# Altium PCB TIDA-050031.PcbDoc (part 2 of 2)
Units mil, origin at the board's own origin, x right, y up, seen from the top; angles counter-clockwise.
Board outline 3300 x 2400 mil, 4 copper layers (Top Layer, Signal Layer 1, Signal Layer 2, Bottom Layer), stack 65.634 mil thick; 87 components, 39 nets, 206 pads, 178 vias.
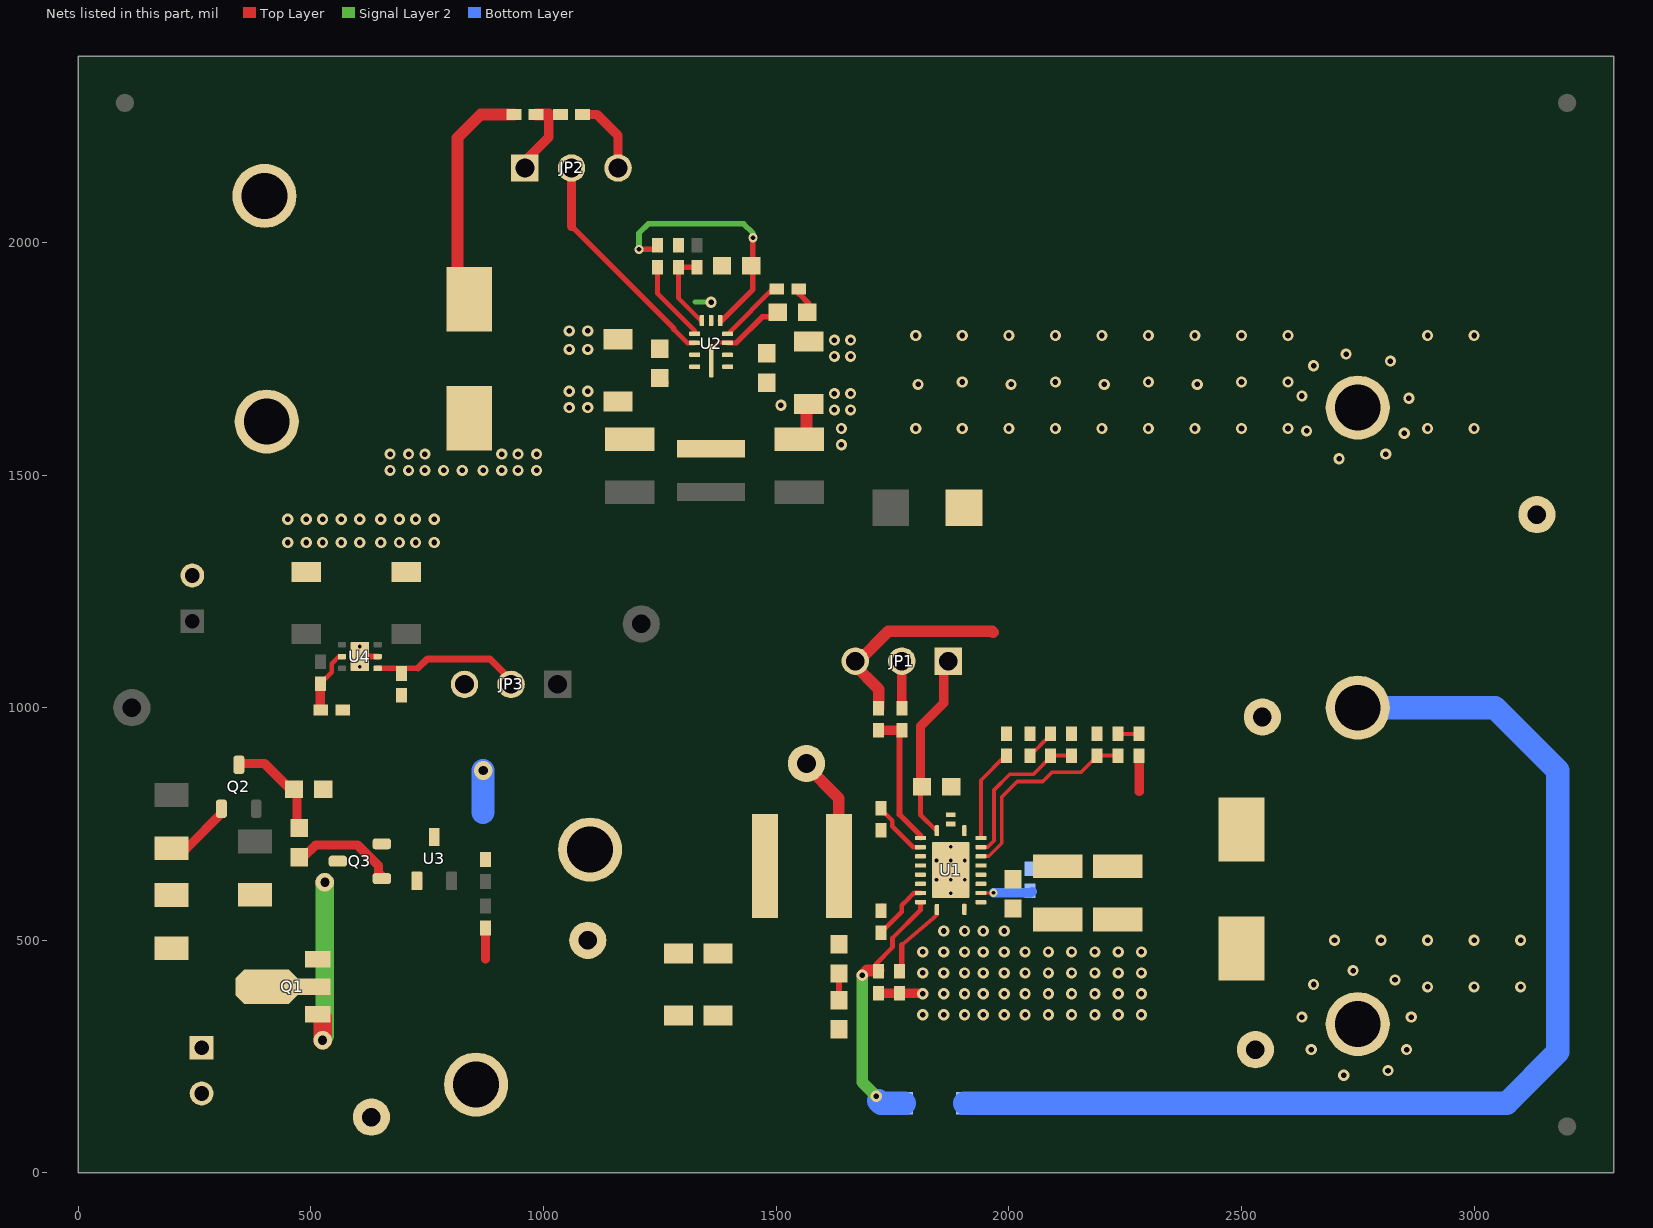
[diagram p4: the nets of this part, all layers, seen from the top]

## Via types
v1: diameter 24, hole 12, Top Layer to Bottom Layer, 156 vias
v2: diameter 19.68, hole 7.87, Top Layer to Bottom Layer, 10 vias
v3: diameter 20, hole 10, Top Layer to Bottom Layer, 4 vias
v4: diameter 24, hole 12, Top Layer to Bottom Layer, tented bottom, 4 vias
v5: diameter 40, hole 20, Top Layer to Bottom Layer, 3 vias
v6: diameter 18, hole 8, Top Layer to Bottom Layer, 1 vias

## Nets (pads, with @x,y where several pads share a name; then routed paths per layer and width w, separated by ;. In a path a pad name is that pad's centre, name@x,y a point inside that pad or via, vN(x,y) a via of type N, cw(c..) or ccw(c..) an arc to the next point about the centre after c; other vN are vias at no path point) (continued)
AGND: C8.2 C10.2 C12.2 C14.1 JP1.3 NT2.2 NT3.2 R2.1 R6.1 U1.20 | length 467.2
  Top Layer w8: C14.1@1876,814.79 C14.1@1876,831 ; U1.20@1904.53,736.47 U1.20@1904.53,735.65 U1.20@1905,735.65 ; C8.2@2043,941 C8.2@2047,945 ; R2.1@2189,945 2189,944 R2.1@2189.38,943.62
  Top Layer w25: JP1.3@1665,1095 1720,1040 C12.2@1720,998.62 ; JP1.3@1670,1100 1677,1100 1741,1164 1964,1164 1966,1162
AGND1: C29.1 JP2.3 NT1.1 R11.1 R13.1 U2.6 | length 203
  Top Layer w20: R11.1@1083.62,2275 1115,2275 1160,2230 JP2.3@1160,2160
  Signal Layer 2 w10: NT1.1@1325,1872 v1@1363,1872
  other v1: 1360,1871.5
BAT+: C20.1 C21.1 C22.1 C23.1 C24.1 J1.1 R10.2 U2.2 U2.10 | length 444
  Top Layer w12: C23.1@1483.39,1758.39 C23.1@1490,1765 ; C21.1@1560,1785 C21.1@1560,1790
  Top Layer w25: C20.1@815,1937.48 815,2225 865,2275 R10.2@936.38,2275
  other v1: 1660,1755 1095,1770 1660,1790 1095,1810
  other v4: 1625,1755 1055,1770 1625,1790 1055,1810
BCKP+: C1.1 C2.1 J5.1 L1.1 Q1.3 R30.2 TP1.1 | length 66.4
  Top Layer w20: 875,460 R30.2@875,526.38
BOOT: C9.2 U1.8 | length 130.6
  Top Layer w10: C9.2@1724,515 1770,561 1770,575 1785.35,590.35 1785.35,590.99 1794.06,599.7 1794.7,599.7 1796.78,601.78 U1.8@1810.04,601.78
BST: R12.1 U2.4 | length 139.9
  Top Layer w10: U2.4@1400,1807 1493,1900 R12.1@1501.38,1900
COMP: C10.1 R5.2 U1.18 | length 340.4
  Top Layer w8: U1.18@1939.96,700.21 1954.14,700.21 1968,714.06 1968,823 2002,857 2053,857 2093,897 C10.1@2135,897
EN: C12.1 R4.1 U1.2 | length 309.5
  Top Layer w10: U1.2@1810.04,719.89 1810.04,724.96
  Top Layer w12: R4.1@1765,955 1765,770 1810.04,724.96
  Top Layer w20: C12.1@1720,951.38 R4.1@1768.62,951.38 ; R4.1@1765,955 R4.1@1770,950
EN2: JP2.2 U2.9 | length 504.7
  Top Layer w10: 1280,1813.03 1309.05,1783.98 U2.9@1324.57,1783.98
  Top Layer w12: 1060,2035 1280,1815 1280,1813.03
  Top Layer w20: 1060,2035 JP2.2@1060,2170
FB: R1.1 R2.2 U1.17 | length 446.8
  Top Layer w8: U1.17@1939.96,680.52 1956.91,680.52 1985,708.62 1985,808 2018.13,841.13 2073.13,841.13 2093,861 2155,861 2191,897 2236,897 R1.1@2238,895
FB2: R13.2 R14.1 U2.7 | length 168
  Top Layer w10: R13.2@1290,1931.38 1290,1880 1337.8,1832.2 U2.7@1340.32,1832.2
  Top Layer w12: R13.2@1285,1950 1288.62,1946.38 R14.1@1330,1946.38
FSW: R3.1 U1.3 | length 129.3
  Top Layer w10: R3.1@1725,784 R3.1@1725,783.62 1725,783 1724,783 1742,765 1742.14,765 1749.68,757.46 1749.68,745.32 1795,700 U1.3@1809.83,700
ILIM: R6.2 U1.19 | length 197.7
  Top Layer w8: U1.19@1939.96,719.89 1939.96,843.96 R6.2@1992,896
MODE: R16.1 U1.13 | length 113
  Top Layer w6: U1.13@1939.96,601.78 v6@1967.22,601.78 ; v6(1967,602) v6@1967.22,601.78 ; v6@1968.06,600.94 v6@1967.22,601.78
  Bottom Layer w20: v6(1967,602) 2047,602 R16.1@2050,605
NetC8_1: C8.1 R5.1 | length 68.1
  Top Layer w8: C8.1@2045,896.38 2088.62,940 R5.1@2095,940
NetC13_1: C13.1 R7.2 | length 49.5
  Top Layer w12: C13.1@1635,379 1635,386.5 R7.2@1635,428.5
NetC15_1: C15.1 D2.1 U1.9 | length 556.2
  Top Layer w10: C15.1@1715,445 1715,450 1750,485 1750,505 1810.04,565.04 U1.9@1810.04,582.1
  Top Layer w25: v1(1685,425) 1695,435 C15.1@1720,435
  Signal Layer 2 w25: v1(1685,425) 1685,195 v1(1715,165)
  Bottom Layer w25: v1(1715,165) v1@1722.5,157.5
  Bottom Layer w50: v1@1720,155 1725,150 D2.1@1775.53,150
NetC25_2: C25.2 R12.2 | length 58.9
  Top Layer w12: R12.2@1548.62,1890 1570,1868.62 C25.2@1570,1840
NetC33_1: C33.1 Q1.2 Q1.4 R32.2 | length 131.9
  Top Layer w25: Q1.4@375,400 Q1.4@404.57,400 Q1.2@506.93,400
NetJP1_2: JP1.2 R4.2 | length 96.4
  Top Layer w20: R4.2@1770,998.62 JP1.2@1770,1095
NetJP2_1: JP2.1 R10.1 R11.2 | length 163.2
  Top Layer w20: JP2.1@960,2160 960,2175 1010.79,2225.79 1010.79,2275
  Top Layer w25: R10.1@983.62,2275 1010.79,2275
NetJP3_2: JP3.2 R34.2 U4.4 | length 316.7
  Top Layer w12: U4.4@643.39,1084.41 643.98,1085 730,1085
  Top Layer w15: 730,1085 750,1105 885,1105 JP3.2@925,1065
  Top Layer w20: JP3.2@925,1065 JP3.2@935,1065
NetQ1_1: Q1.1 Q3.3 R28.2 U3.1 | length 394.1
  Top Layer w40: v5(525,285) Q1.1@525,335
  Signal Layer 2 w20: v5@520,285 v5@530,295
  Signal Layer 2 w40: v5@530,295 v5(530,625)
NetQ2_1: Q2.1 R31.2 R32.1 | length 141.9
  Top Layer w20: R31.2@200,697.91 232.91,697.91 Q2.1@310,775
NetQ2_3: Q2.3 R27.1 R33.2 | length 202.7
  Top Layer w20: 357.76,880 400,880 R33.2@455,825 ; R33.2@463.5,825 470,818.5 R27.1@470,745
NetQ3_1: Q3.1 R27.2 | length 228.8
  Top Layer w20: R27.2@475,678.5 483.5,678.5 510,705 600,705 645,660 645,645 Q3.1@655,635
NetR1_2: R1.2 R9.1 | length 52.6
  Top Layer w8: R1.2@2235,943.62 2278.62,943.62 R9.1@2285,950
NetR35_2: R35.2 R36.1 U4.2 | length 131.6
  Top Layer w10: R36.1@520,1051.38 544.88,1076.26 544.88,1094.88 U4.2@560,1110
  Top Layer w20: R35.2@520,995 R36.1@520,1051.38
PG: R15.1 U2.8 | length 160.7
  Top Layer w10: R15.1@1245,1931.38 1245,1890 1324.57,1810.43 U2.8@1324.57,1803.66
PGND: C1.2 C2.2 C3.2 C4.2 C5.2 C11.1 C13.2 C15.2 C20.2 C21.2 C22.2 C23.2 C24.2 C26.2 C27.2 C28.2 C30.2 C31.2 C32.2 C33.2 J2.1 J4.1 J6.1 J7.1 JP3.3 NT1.2 NT2.1 NT3.1 Q3.2 R16.2 R29.1 R33.1 R34.1 R35.1 TP2.1 TP4.1 TP6.1 U1.11 U1.12 U1.21@1875,651 U2.1 U2.11 U3.3 U4.5 U4.7@605,1110 | length 382.6
  Top Layer w10: U2.1@1395.43,1732.8 U2.1@1397.2,1732.8 ; C13.2@1630,299 C13.2@1631,298 ; U1.21@1875,600 1875,605 U1.21@1875,651 ; U1.21@1877,701 U1.21@1881,705 ; U1.11@1904.53,566.35 U1.11@1904.53,575.47
  Top Layer w12: U4.7@610,1110 U4.5@643.39,1110 ; C24.2@1255,1698.5 C24.2@1263.5,1698.5
  Top Layer w20: C15.2@1720,386.38 1813.62,386.38 v1(1815,385)
  Top Layer w25: C27.2@1550,1577.09 1562.09,1577.09 1565,1580 C21.2@1565,1650
  Bottom Layer w50: 870,775 v5(870,865)
  other v1: 2720,210 2815,220 2650,265 2855,265 2630,335 2865,335 1815,340 1860,340 1905,340 1945,340 1990,340 2035,340 2085,340 2135,340 2185,340 2235,340 2285,340 1860,385 1905,385 1945,385 1990,385 2035,385 2085,385 2135,385 2185,385 2235,385 2285,385 2900,400 3000,400 3100,400 2655,405 2830,415 1815,430 1860,430 1905,430 1945,430 1990,430 2035,430 2085,430 2135,430 2185,430 2235,430 2285,430 2740,435 1815,475 1860,475 1905,475 1945,475 1990,475 2035,475 2085,475 2135,475 2185,475 2235,475 2285,475 2700,500 2800,500 2900,500 3000,500 3100,500 1860,520 1905,520 1945,520 1990,520 450,1355 490,1355 525,1355 565,1355 605,1355 650,1355 690,1355 725,1355 765,1355 450,1405 490,1405 525,1405 565,1405 605,1405 650,1405 690,1405 725,1405 765,1405 670,1510 710,1510 745,1510 785,1510 825,1510 870,1510 910,1510 945,1510 985,1510 2710,1535 670,1545 710,1545 745,1545 910,1545 945,1545 985,1545 2810,1545 1640,1565 2850,1590 2640,1595 1640,1600 1800,1600 1900,1600 2000,1600 2100,1600 2200,1600 2300,1600 2400,1600 2500,1600 2600,1600 2900,1600 3000,1600 1625,1640 1660,1640 1055,1645 1095,1645 1510,1650 2860,1665 2630,1670 1625,1675 1660,1675 1055,1680 1095,1680 1805,1695 2005,1695 2205,1695 2405,1695 1900,1700 2100,1700 2300,1700 2500,1700 2600,1700 2655,1735 2820,1745 2725,1760 1800,1800 1900,1800 2000,1800 2100,1800 2200,1800 2300,1800 2400,1800 2500,1800 2600,1800 2900,1800 3000,1800
  other v2: 1875,600.8 1844.49,630.33 1875,630.33 1905.51,630.33 1844.49,671.67 1875,671.67 1905.51,671.67 1875,701.2 605,1088.35 605,1131.65
SS: C11.2 U1.10 | length 160.8
  Top Layer w8: 1770,490 1836.9,546.9 1845.48,555.48 U1.10@1845.48,566.35
  Top Layer w12: C11.2@1770,440 1770,490
SW: C9.1 L1.2 R3.2 R7.1 TP7.1 U1.4 U1.5 U1.6 U1.7 | length 253
  Top Layer w10: C9.1@1726,563.62 C9.1@1726,565
  Top Layer w12: L1.2@1645,655 L1.2@1645,660 ; C9.1@1726,571 C9.1@1728,573
  Top Layer w25: TP7.1@1565,875 1634.5,805.5 L1.2@1634.5,660
SW1: C25.1 L2.1 U2.3 U2.12 | length 181.4
  Top Layer w8: U2.12@1360,1746.06 1360,1770 1375,1785 U2.3@1400,1785
  Top Layer w10: U2.3@1395.43,1783.98 1413.98,1783.98
  Top Layer w12: 1413.98,1783.98 1470,1840 1483.5,1840
Vcc: C14.2 JP1.1 U1.1 | length 404.4
  Top Layer w10: C14.2@1810,830 1810,770 U1.1@1845,735
  Top Layer w20: C14.2@1810,830 1810,960 1860,1010 1860,1090 JP1.1@1870,1100
Vcc2: C29.2 R15.2 U2.5 | length 549.2
  Top Layer w12: v3(1205,1985) R15.2@1238.62,1985 ; U2.5@1379.68,1832.2 1383.2,1832.2 1450,1899 v3(1450,2010)
  Signal Layer 2 w12: v3(1205,1985) 1205,2020 1225,2040 1430,2040 1450,2020 v3(1450,2010)
Vout: C3.1 C4.1 C5.1 C30.1 D1.1 D2.2 J3.1 R9.2 TP3.1 U1.14 U1.15 U1.16 | length 2483.4
  Top Layer w20: 2280,820 R9.2@2280,896.38
  Bottom Layer w50: D2.2@1904.47,150 3070,150 3180,260 3180,295 ; J3.1@2750,1000 3045,1000 3180,865 3180,300
pads on no net: FID1.1 FID2.1 FID3.1 U1.21@1852.95,609.66 U1.21@1852.95,651 U1.21@1852.95,692.34 U1.21@1897.05,609.66 U1.21@1897.05,651 U1.21@1897.05,692.34 U4.3 U4.7@605,1092.28 U4.7@605,1127.72

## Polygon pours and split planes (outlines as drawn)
AGND1 on Top Layer "TOP_LAYER_AGND1_P030" (solid, remove dead copper, pour order 30): 1130,2025 1130,2250 1550,2250 1550,2035 1410,2035 1410,1909 1360,1909 1360,1965 1385,1990 1385,2025 1300,2025 1300,1980 1275,1980 1275,2025
SW on Top Layer "TOP_LAYER_SW_P000" (solid, remove dead copper, pour order 0): 1821,690 1821,618 1819,616 1788,616 1735,563 1735,548 1714,548 1675,509 1675,476 1603,476 1603,770 1695,770 1775,690
BAT+ on Top Layer "TOP_LAYER_BAT+_P010" (solid, remove dead copper, pour order 10): 50,2200 830,2200 1130,1900 1160,1900 1290,1770 1340,1770 1340,1750 1310,1750 1300,1750 1290,1750 50,1750
PGND on Top Layer "TOP_LAYER_PGND_P012" (solid, remove dead copper, pour order 12): 50,1735 1305,1735 1310,1740 1340,1740 1340,1730 1250,1640 1250,1530 1130,1530 1100,1500 1100,1254.83 50,1255.28
BAT+ on Top Layer "TOP_LAYER_BAT+_P014" (solid, remove dead copper, pour order 14): 1385,1770 1428,1770 1468,1810 1675,1810 1675,1740 1420,1740 1410,1750 1385,1750
SW1 on Top Layer "TOP_LAYER_SW1_P018" (solid, remove dead copper, pour order 18): 1350,1784 1370,1784 1370,1730 1460,1640 1460,1538 1260,1538 1260,1642 1350,1732
AGND1 on Top Layer "TOP_LAYER_AGND1_P022" (solid, remove dead copper, pour order 22): 1370,1845 1409.78,1884.78 1410.12,1916 1351,1916 1310,1916 1310,1880 1359,1831 1370,1831
9V on Top Layer "TOP_LAYER_9V_P026" (solid, remove dead copper, pour order 26): 1118,1499.99 1785,1499.99 1785,1187.01 1118,1186.95
9V on Top Layer "TOP_LAYER_9V_P038" (solid, remove dead copper, pour order 38): 635,1230 1600,1230 1600,1130 635,1130
5V on Top Layer "TOP_LAYER_5V_P040" (solid, remove dead copper, pour order 40): 575,1115 550,1115 525,1090 400,1090 275,965 275,780 50,780 50,1215 65,1230 575,1230
PGND on Top Layer "TOP_LAYER_PGND_P042" (solid, remove dead copper, pour order 42): 585,1285 625,1285 625,1070 855,1070 855,975 555,975 555,1025 585,1055
NetQ2_1 on Top Layer "TOP_LAYER_NETQ2_1_P044" (solid, remove dead copper, pour order 44): 50,725 250,725 250,570 50,570
NetC33_1 on Top Layer "TOP_LAYER_NETC33_1_P046" (solid, remove dead copper, pour order 46): 50,515 385,515 450,450 450,265 410,225 50,225
NetQ1_1 on Top Layer "TOP_LAYER_NETQ1_1_P048" (solid, remove dead copper, pour order 48): 335,620 490,620 540,670 575,670 600,645 600,605 610,595 695,595 710,610 710,645 740,645 740,535 335,535
PGND on Top Layer "TOP_LAYER_PGND_P050" (solid, remove dead copper, pour order 50): 515,900 900,900 900,665 695,665 600,760 515,760
BCKP+ on Top Layer "TOP_LAYER_BCKP+_P052" (solid, remove dead copper, pour order 52): 484.82,480.18 894.82,480.18 944.82,530.18 944.82,775.18 1534.82,775.18 1534.82,460.18 1489.82,415.18 1234.82,415.18 1139.82,320.18 570,320.18 570,405 545,430 484.82,430
PGND on Top Layer "TOP_LAYER_PGND_P054" (solid, remove dead copper, pour order 54): 1145,50 1145,280 1240,375 1550,375 1590,335 1780,335 1800,355 1800,490 1860,550 1860,749 1890,749 1890,625 1930,585 2055,585 2065,595 3250,595 3250,200 3100,200 3100,50
AGND on Top Layer "TOP_LAYER_AGND_P056" (solid, remove dead copper, pour order 56): 1925,726 1925,885 1965,925 2210,925 2210,1174 1945,1174 1945,1060 1855,970 1855,726
Vout on Top Layer "TOP_LAYER_VOUT_P058" (solid, remove dead copper, pour order 58): 1931,666 1970,666 2015,711 2015,789 2054,828 2313,828 2329,844 2329,1199 1881,1199 1875,1205 1875,1500 3235,1500 3235,615 2045,615 1930,615 1930,665
PGND on Top Layer "TOP_LAYER_PGND_P062" (solid, remove dead copper, pour order 62): 1380,1740 1411,1740 1420,1731 1420,1730 1690,1730 1715,1755 1715,2225 3250,2225 3250,1530 1475,1530 1475,1645 1400,1720 1385,1720 1380,1725
PGND on Top Layer "TOP_LAYER_PGND_P074" (solid, remove dead copper, pour order 74): 50,290 1165,290 1165,50 50,50
BAT+ on Signal Layer 2 "SIGNAL_LAYER_2_BAT+_P016" (solid, remove dead copper, pour order 16): 1040,1835 1675,1835 1675,1730 1040,1730
PGND on Signal Layer 2 "SIGNAL_LAYER_2_PGND_P078" (solid, remove dead copper, pour order 78): 50,2100 3250,2100 3250,100 1350,100 1350,1220 1130,1440 50,1440
PGND on Bottom Layer "BOTTOM_LAYER_PGND_P070" (solid, remove dead copper, pour order 70): 365,1200 585,1200 585,1080 595,1070 765,1070 765,50 150,50 50,50 50,1200
PGND on Bottom Layer "BOTTOM_LAYER_PGND_P064" (solid, remove dead copper, pour order 64): 50,2100 3200,2100 3200,1150 50,1150
PGND on Bottom Layer "BOTTOM_LAYER_PGND_P072" (solid, remove dead copper, pour order 72): 750,785 3115,785 3115,50 750,50
PGND on Signal Layer 1 "SIGNAL_LAYER_1_PGND_P080" (solid, remove dead copper, pour order 80): 50,2100 3250,2100 3250,100 1350,100 1350,1380 1290,1440 50,1440
PGND on Signal Layer 1 "SIGNAL_LAYER_1_PGND_P084" (solid, remove dead copper, pour order 84): 330,1230 560,1230 560,1015 330,1015

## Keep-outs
Keep-Out Layer:
  text ".Layer_Name" at 577,-858.49 h60

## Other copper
Top Layer:
  pour cut-out: 45,1470 420,1470 420,1450 45,1450
  pour cut-out: 625,1070 720,1070 720,1035 625,1035
  text ".Layer_Name" at 577,-858.49 h60
Bottom Layer:
  pour cut-out: 45,1470 420,1470 420,1450 45,1450
  pour cut-out: 800,785 850,785 850,405 800,405
  text ".Layer_Name" at 577,-858.49 h60

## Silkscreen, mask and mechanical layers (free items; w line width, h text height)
Top Overlay:
  text "VIN" at 90,2065 h50
  text "ON" at 935,2050 h40
  text "OFF" at 1105,2050 h40
  text "TIDA-050031" at 1950,2020 h70
  text "EN" at 1025,2000 h40
  text "PGND" at 2900,1660 h50
  text "PGND" at 90,1605 h50
  text "EN" at 1730,1185 h40
  text "VCC" at 1850,1185 h40
  text "AGND" at 1530,1180 h40
  text "VOUT" at 2875,955 h50
  text "OFF" at 790,945 h40
  text "ON" at 1000,940 h40
  text "EN" at 905,915 h40
  text "BACKUP+" at 970,825 h50
  text "PGND" at 2900,290 h50
  text "PGND" at 760,20 h50
  text ".Layer_Name" at 577,-858.49 h60
Bottom Overlay:
  text ".Layer_Name" at 577,-858.49 h60
Top Paste:
  text ".Layer_Name" at 577,-858.49 h60
Bottom Paste:
  text ".Layer_Name" at 577,-858.49 h60
Top Solder:
  text ".Layer_Name" at 577,-858.49 h60
  text ".Layer_Name" at 577,-858.49 h60
Bottom Solder:
  text ".Layer_Name" at 577,-858.49 h60
Drill Guide:
  text ".Layer_Name" at 577,-858.49 h60
M1 Board Outline:
  lines w10: 0,0 0,2400 ; 0,0 3300,0 ; 0,0 0,2400 ; 0,0 3300,0 ; 0,2400 3300,2400 ; 0,2400 3300,2400 ; 3300,0 3300,2400 ; 3300,0 3300,2400
  text ".Layer_Name" at 577,-858.49 h60
M2 Board Dimensions:
  rectangle: 0,-275 125,-150
  rectangle: 125,-400 500,-275
  lines w7: 0,-275 1000,-275 ; 125,-400 125,-150 ; 250,-400 250,-150 ; 500,-400 500,-150 ; 750,-400 750,-150 ; 0,-400 1000,-400 1000,-150 0,-150 0,-400
  text ".Layer_Name" at 577,-858.49 h60
M3 3D STEP Top:
  text ".Layer_Name" at 577,-858.49 h60
M4 3D STEP Bottom:
  text ".Layer_Name" at 577,-858.49 h60
M5 Assembly Top:
  lines w10: -292,-930.17 6308,-930.17 ; -292,-726.83 6310,-726.83 ; -292,-523.5 -292,-1133.5 3713,-1133.5 6310,-1133.5 6310,-523.5 -291.5,-523.5 -291.5,-1133.5 1284,-1133.5 ; 2173,-1133.5 2173,-523.5 ; 3440,-726.83 3440,-523.5 ; 4280,-726.83 4280,-523.5 ; 4902,-1140 4902,-937.17
  text "COMPONENTS MARKED 'DNP' SHOULD NOT BE POPULATED." at 1153.5,-318.5 h60
  text "ASSEMBLY VARIANT:" at 1153,-434 h60
  text ".VariantName" at 2189,-434 h60
  text "PCB VIEWED FROM TOP SIDE" at -228.5,-655.67 h60
  text "BOARD #:" at 2248,-655.67 h60
  text ".PRJ_Number" at 2793.5,-655.67 h60
  text "REV:" at 3638,-655.67 h60
  text ".PCB_Rev" at 3929.5,-655.67 h60
  text "SVN REV:" at 4476,-655.67 h60
  text ".VersionControl_RevNumber" at 4982,-655.67 h60
  text "TID #:" at 2248,-859 h60
  text ".TID" at 2793.5,-859 h60
  text "PLOT NAME =" at -228.5,-1064.34 h60
  text ".plot_File_Name" at 577,-1064.34 h60
  text "GENERATED    :" at 2250,-1064.34 h60
  text ".Print_Date" at 3119.5,-1064.34 h60
  text ".Print_Time" at 3848.5,-1064.34 h60
  text "TEXAS INSTRUMENTS" at 5113,-1064.34 h60
M6 Assembly Bottom:
  lines w10: -292.5,-727.33 6309.5,-727.33 ; -290.5,-930.67 6309.5,-930.67 ; 1115.5,-1140.5 1115.5,-937.67 ; 1737.5,-727.33 1737.5,-524 ; 2577.5,-727.33 2577.5,-524 ; 3844.5,-1134 3844.5,-524 ; 4733.5,-1134 6309,-1134 6309,-524 -292.5,-524 -292.5,-1134 2304.5,-1134 6309.5,-1134 6309.5,-524
  text "COMPONENTS MARKED 'DNP' SHOULD NOT BE POPULATED." at 6102,-318 h60
  text ".VariantName" at 5058,-434 h60
  text "ASSEMBLY VARIANT:" at 6097,-434 h60
  text ".VersionControl_RevNumber" at 1035.5,-656.17 h60
  text "SVN REV:" at 1541.5,-656.17 h60
  text ".PCB_Rev" at 2088,-656.17 h60
  text "REV:" at 2379.5,-656.17 h60
  text ".PRJ_Number" at 3224,-656.17 h60
  text "BOARD #:" at 3769.5,-656.17 h60
  text "PCB VIEWED FROM BOTTOM SIDE" at 6246,-656.17 h60
  text ".TID" at 3224,-859.5 h60
  text "TID #:" at 3769.5,-859.5 h60
  text "TEXAS INSTRUMENTS" at 904.5,-1064.84 h60
  text ".Print_Time" at 2169,-1064.84 h60
  text ".Print_Date" at 2898,-1064.84 h60
  text "GENERATED    :" at 3767.5,-1064.84 h60
  text ".plot_File_Name" at 5440.5,-1064.84 h60
  text "PLOT NAME =" at 6246,-1064.84 h60
M9 Title Sheet:
  drawing of 57 lines, arcs and shapes, not listed
  text "1" at 739.84,8036.5 h70
  text "2" at 3235.5,8036.5 h70
  text "3" at 5724.84,8036.5 h70
  text "4" at 8231.51,8036.5 h70
  text "5" at 10730.5,8036.5 h70
  text "6" at 13235.5,8036.5 h70
  text "A" at -416.5,6893.5 h70
  text "A" at 14383.5,6893.5 h70
  text "B" at -416.5,4513.5 h70
  text "B" at 14383.5,4513.5 h70
  text "C" at -416.5,2138.5 h70
  text "C" at 14383.5,2138.5 h70
  text "PROJECT TITLE:" at 11343.5,277.5 h45
  text ".PRJ_Title" at 11393.5,144.17 h70
  text "DESIGNED FOR:" at 11343.5,-23.5 h45
  text ".PRJ_Customer" at 11393.5,-163.5 h70
  text "D" at -416.5,-231.5 h70
  text "D" at 14383.5,-231.5 h70
  text "FILE NAME:" at 11343.5,-323.5 h45
  text ".PCB_File_Name_No_Path" at 11393.5,-443.5 h70
  text "Texas Instruments (TI) and/or its licensors do not warrant the accuracy or completeness of this specification" at 6374,-605.34 h45
  text "ENGINEER:" at 11343.5,-613.5 h45
  text "LAYOUT BY:" at 12848.5,-613.5 h45
  text "or any information contained therein. TI and/or its licensors do not warrant that this design will meet" at 6329.01,-718 h45
  text ".PRJ_Engineer" at 11393.5,-768.49 h70
  text ".PCB_Layout" at 12899,-768.49 h70
  text "the specifications, will be suitable for your application or fit for any particular purpose, or will operate in" at 6329.01,-830.67 h45
  text ".Layer_Name" at 577,-858.49 h60
  text "ALTIUM DESIGNER VERSION:" at 12848.5,-923.5 h45
  text "an implementation. TI and/or its licensors do not warrant that the design is production worthy. You should" at 6329.01,-943.33 h45
  text "completely validate and test your design implementation to confirm the system functionality for your application." at 6374,-1056 h45
  text ".print_Scale" at 11393.5,-1056.83 h70
  text ".Application_BuildNumber" at 12899,-1056.83 h70
  text "1" at 739.84,-1263.5 h70
  text "2" at 3235.5,-1263.5 h70
  text "3" at 5724.84,-1263.5 h70
  text "4" at 8231.51,-1263.5 h70
  text "5" at 10730.5,-1263.5 h70
  text "6" at 13235.5,-1263.5 h70
M10 Fab Notes:
  drawing of 189 lines, arcs and shapes, not listed
  text "DESIGN INFORMATION" at 12382.02,6356.17 h60
  text "MIN. TRACK WIDTH:" at 11737.46,6224.05 h60
  text "8" at 12833.7,6224.05 h60
  text "MIL" at 12988.46,6224.05 h60
  text "MIN. CLEARANCE:" at 11737.46,6099.92 h60
  text "0.2" at 12773.7,6099.93 h60
  text "mm" at 12988.46,6099.92 h60
  text "MIN. VIA PAD SIZE:" at 11737.46,5975.8 h60
  text "24" at 12803.71,5975.8 h60
  text "MIL" at 12988.46,5975.8 h60
  text "0.05mm (2MIL)" at 12432.46,5845.9 h60
  text "MINIMUM ANNULAR RING" at 11408.23,5837.67 h60
  text "EXTERNAL" at 13140.46,5837.67 h60
  text "PER" at 11608.23,5727.55 h60
  text "IPC-D-275 CLASS 2 LEVEL C" at 11828.23,5727.54 h60
  text "MIL, HOLES" at 13316.46,5627.07 h60
  text "+/-" at 12924,5618.48 h60
  text "+/-" at 13778,5618.48 h60
  text "REGISTRATION TOLERANCES:" at 11408.23,5617.42 h60
  text "METAL" at 12608,5617.42 h60
  text "5" at 13184.2,5617.42 h60
  text "3" at 14017.2,5617.42 h60
  text "MIL" at 14133.46,5617.42 h60
  text "HOLE SIZE TOLERANCE (UNLESS OTHERWISE SPECIFIED):" at 11408.23,5519.1 h60
  text "+/-" at 13778,5516.23 h60
  text "3" at 14017.2,5515.17 h60
  text "MIL" at 14133.46,5515.17 h60
  text "MATERIAL:" at 11333.46,5377.52 h60
  text "FR-4 High Tg" at 12319.9,5249 h60
  text "X" at 12175.46,5241.01 h60
  text "FR-408" at 11754.46,5236.49 h60
  text "OTHER" at 13242.46,5236.49 h60
  text "62 MIL (1.6mm) +/-10%" at 12074.56,5093.46 h60
  text "X" at 11954.46,5091.01 h60
  text "THICKNESS:" at 11408.23,5085.24 h60
  text "OTHER" at 13359.46,5085.24 h60
  text "TOLERANCE:" at 11408.23,4946.92 h60
  text "X" at 12256.46,4946.92 h60
  text "ANSI IPC-6012 TYPE 3 CLASS 2" at 12434.48,4946.92 h60
  text "OTHER +/-" at 12434.46,4802.73 h60
  text "BOW & TWIST:" at 11408.23,4657.54 h60
  text "X" at 12256.46,4657.54 h60
  text "ANSI IPC-6012 TYPE 3 CLASS 2" at 12434.48,4657.54 h60
  text "OTHER +/-" at 12434.46,4510.85 h60
  text "DRILLING:" at 11333.46,4380.23 h60
  text "NC_DRILL FILES" at 13094.46,4275.04 h60
  text "REFERENCE:" at 11408.23,4271.1 h60
  text "X" at 12065.46,4271.01 h60
  text "AS SHOWN" at 12243.46,4271.1 h60
  text "X" at 12966.46,4271.1 h60
  text "OTHER" at 13392.46,4128.85 h60
  text "PTH COPPER THICKNESS:" at 11407.91,4125.32 h60
  text "X" at 12547.14,4125.32 h60
  text "20-30 um" at 12675.14,4125.32 h60
  text "BOARD FINISH:" at 11333.46,3977.73 h60
  text "SILKSCREEN:" at 11488.68,3867.6 h60
  text "X" at 12446.46,3867.6 h60
  text "TOP" at 12563.46,3867.6 h60
  text "X" at 12956.46,3867.6 h60
  text "BOTTOM" at 13074.46,3867.6 h60
  text "SILKSCREEN COLOR:" at 11488.68,3712.41 h60
  text "X" at 12445.46,3712.41 h60
  text "WHITE" at 12563.46,3712.41 h60
  text "OTHER" at 13074.46,3712.41 h60
  text "X" at 12576.46,3568.96 h60
  text "GREEN" at 12694.46,3568.96 h60
  text "OTHER" at 13312.46,3568.96 h60
  text "SOLDER RESIST COLOR:" at 11488.68,3562.1 h60
  text "X" at 12576.46,3414.71 h60
  text "MATTE" at 12694.46,3414.71 h60
  text "SEMI-GLOSS" at 13312,3414.07 h60
  text "IMMERSION GOLD (ENIG)" at 12394.46,3241.94 h60
  text "ENEPIG" at 13732,3234.72 h60
  text "SURFACE FINISH:" at 11333.46,3233.72 h60
  text "X" at 12216.46,3233.72 h60
  text "IMM. TIN/SILVER OR EQUIV" at 11663,3096.4 h60
  text "OTHER" at 13094.46,3092.47 h60
  text "ARRAY/PANEL:" at 11333.46,2937.09 h60
  text "CUT AND TRIM PER M1 BOARD OUTLINE" at 12394.46,2928.87 h60
  text "N.C. ROUTE" at 12394.46,2792.9 h60
  text "X" at 13082.46,2792.9 h60
  text "V. SCORE" at 13260.46,2792.9 h60
  text "CERTIFICATION:" at 11333.46,2663.77 h60
  text "MATERIALS AND WORKMANSHIP FOR ALL PCBS" at 12058.46,2663.77 h60
  text "TO MEET OR EXCEED THE REQUIREMENTS OF:" at 12058.46,2569.71 h60
  text "X" at 11695.97,2441.08 h60
  text "ANSI IPC-A-600F CLASS ->" at 11823.96,2441.08 h60
  text "X" at 13471.97,2441.08 h60
  text "2" at 13581.96,2441.08 h60
  text "1" at 13266.96,2439.58 h60
  text "3" at 13935.96,2439.58 h60
  text "X" at 12507.97,2293.39 h60
  text "RoHS" at 12635.96,2293.39 h60
  text "OTHER" at 13280.36,2293.39 h60
  text "PER ORDER" at 13677.42,2293.39 h60
  text "ALL BOARDS MUST MEET OR EXCEED UL94-V0 REQUIREMENTS." at 11361,2139.57 h60
  text "PCB MUST BEAR THE UL94V-0 UL REGISTERED MATERIAL ID NUMBER" at 11361,2023.5 h60
  text "ADDITIONAL REQUIREMENTS:" at 11333.46,1854.08 h60
  text "MICROSECTION:" at 11408.23,1746.95 h60
  text "YES" at 12313.96,1746.95 h60
  text "REQUIRED" at 13175.46,1602.62 h60
  text "BARE BOARD ELEC. TEST:" at 11408.23,1599.76 h60
  text "NONE" at 12713.96,1599.76 h60
  text "X" at 13057.46,1599.76 h60
  text "PER ORDER" at 13767.46,1599.76 h60
  text "XX MIL VIAS REQUIRE NON-CONDUCTIVE FILL AND PLANARIZE" at 11576.38,1394.82 h59
  text "XX MIL VIAS REQUIRE CONDUCTIVE FILL AND PLANARIZE" at 11584.38,1290.84 h60
  text "OUTER XX MIL TRACES REQUIRE 50 OHM SINGLE-ENDED IMPEDANCE" at 11583.39,1127.46 h58
  text "LAYER 2 & 3 (INNER LAYERS) XX MIL WIDE, XX MIL SPACE / TRACES REQUIRE 100 OHM DIFFERENTIAL IMPEDANCE" at 11575.39,891.74 h60
  text ".Layer_Name" at 577,-858.49 h60
M11 Gerber Information:
  lines w10: -292,-930.17 6308,-930.17 ; -292,-726.83 6310,-726.83 ; -292,-523.5 -292,-1133.5 3713,-1133.5 6310,-1133.5 6310,-523.5 -291.5,-523.5 -291.5,-1133.5 1284,-1133.5 ; 2173,-1133.5 2173,-523.5 ; 3440,-726.83 3440,-523.5 ; 4280,-726.83 4280,-523.5 ; 4902,-1140 4902,-937.17
  text "ALL ARTWORK VIEWED FROM TOP SIDE" at -228.5,-655.67 h60
  text "BOARD #:" at 2248,-655.67 h60
  text ".PRJ_Number" at 2793.5,-655.67 h60
  text "REV:" at 3638,-655.67 h60
  text ".PCB_Rev" at 3929.5,-655.67 h60
  text "SVN REV:" at 4476,-655.67 h60
  text ".VersionControl_RevNumber" at 4982,-655.67 h60
  text "LAYER NAME =" at -228.5,-858.49 h60
  text "TID #:" at 2248,-859 h60
  text ".TID" at 2793.5,-859 h60
  text "PLOT NAME =" at -228.5,-1064.34 h60
  text ".plot_File_Name" at 577,-1064.34 h60
  text "GENERATED    :" at 2250,-1064.34 h60
  text ".Print_Date" at 3119.5,-1064.34 h60
  text ".Print_Time" at 3848.5,-1064.34 h60
  text "TEXAS INSTRUMENTS" at 5113,-1064.34 h60
M12 Stackup:
  drawing of 191 lines, arcs and shapes, not listed
  text "Layer" at 9797.84,7830 h60
  text "Name" at 10207.76,7830 h60
  text "Material" at 11137.5,7830 h60
  text "Thickness" at 11997.27,7830 h60
  text "Constant" at 12647.1,7830 h60
  text "Board Layer Stack" at 13216.96,7830 h60
  text "1" at 9797.84,7710 h60
  text "Top Overlay" at 10207.76,7710 h60
  text "2" at 9797.84,7590 h60
  text "Top Solder" at 10207.76,7590 h60
  text "Solder Resist" at 11137.5,7590 h60
  text "0.40mil" at 11997.27,7590 h60
  text "3.5" at 12647.1,7590 h60
  text "3" at 9797.84,7470 h60
  text "Top Layer" at 10207.76,7470 h60
  text "Copper" at 11137.5,7470 h60
  text "1.40mil" at 11997.27,7470 h60
  text "4" at 9797.84,7350 h60
  text "Dielectric1" at 10207.76,7350 h60
  text "FR-4" at 11137.5,7350 h60
  text "59.20mil" at 11997.27,7350 h60
  text "4.8" at 12647.1,7350 h60
  text "5" at 9797.84,7230 h60
  text "Bottom Layer" at 10207.76,7230 h60
  text "Copper" at 11137.5,7230 h60
  text "1.40mil" at 11997.27,7230 h60
  text "6" at 9797.84,7110 h60
  text "Bottom Solder" at 10207.76,7110 h60
  text "Solder Resist" at 11137.5,7110 h60
  text "0.40mil" at 11997.27,7110 h60
  text "3.5" at 12647.1,7110 h60
  text "7" at 9797.84,6990 h60
  text "Bottom Overlay" at 10207.76,6990 h60
  text ".Layer_Name" at 577,-858.49 h60
M13 Component Bodies Top:
  text ".Layer_Name" at 577,-858.49 h60
M14 Component Bodies Bottom:
  text ".Layer_Name" at 577,-858.49 h60
M15 Courtyards Top:
  text ".Layer_Name" at 577,-858.49 h60
M16 Courtyards Bottom:
  text ".Layer_Name" at 577,-858.49 h60
Drill Drawing:
  text ".Layer_Name" at 577,-858.49 h60
M17 Embedded Cavity:
  text ".Layer_Name" at 577,-858.49 h60
M18 Embedded Assembly:
  text ".Layer_Name" at 577,-858.49 h60
M19 Embedded Keepout:
  text ".Layer_Name" at 577,-858.49 h60

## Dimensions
0,-400 to 1000,-400 on M2 Board Dimensions
0,0 to 0,2400 on M2 Board Dimensions
0,0 to 3300,0 on M2 Board Dimensions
